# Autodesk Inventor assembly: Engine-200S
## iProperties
Created: 2008-02
Part Number: Engine-200S
Description: iAssembly of Engine MKII
Document SubType Name: Assembly
Designer: hendert
Manufacturer: Standard
Standards Organization: Custom
Weld Material: Default
Mass: 280.068 g
Surface Area: 1061.57 cm^2
Volume: 67.1571 cm^3
Density: 4.17035 g/cm^3
DriveMe: 0,0 deg
Author: hendert
